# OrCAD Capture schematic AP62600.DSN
size Custom; title: 4.5V TO 18V INPUT, 6A SYNCHRONOUS BUCK CONVERTER; rev: 1.0; note: DS42003 Rev. 2 - 2
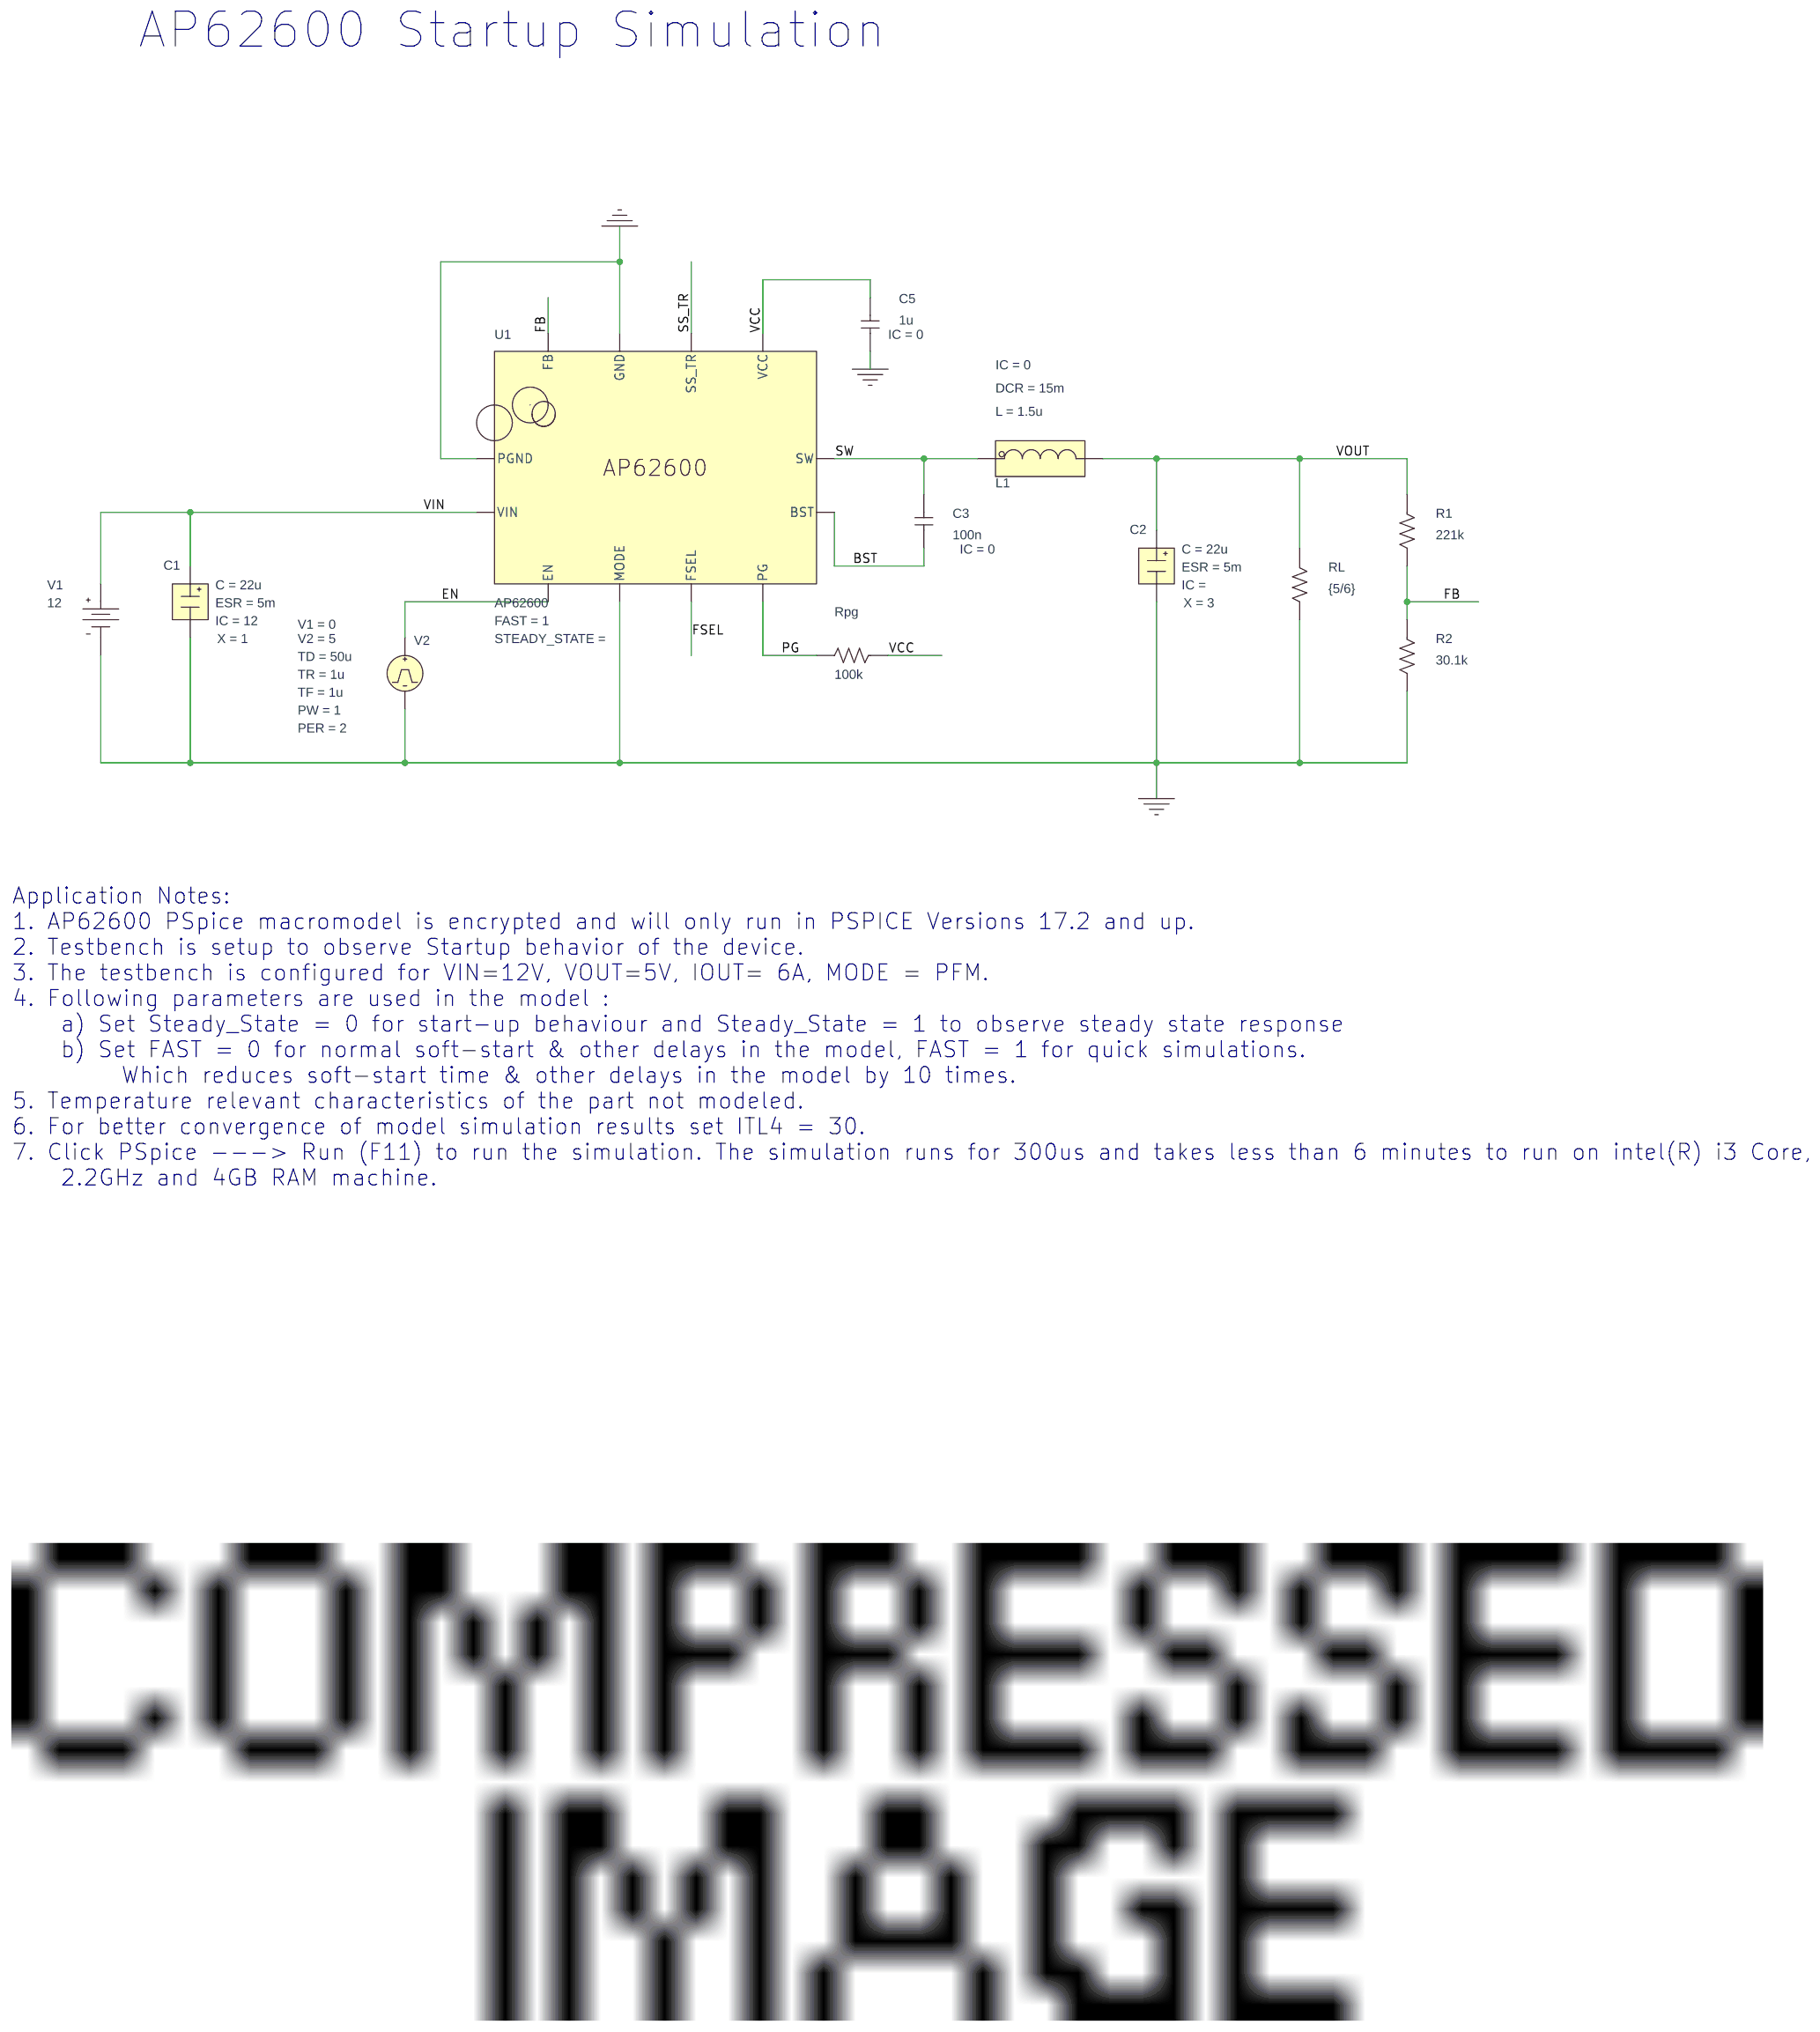
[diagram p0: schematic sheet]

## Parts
C1  CESR
C2  CESR
C3  100n  [RAD/CK05]
C5  1u  [RAD/CK05]
L1  LDCR
R1  221k  [AX/RC05]
R2  30.1k  [AX/RC05]
RL  {5/6}  [AX/RC05]
Rpg  100k  [AX/RC05]
U1  AP62600
V1  VDC
V2  VPULSE

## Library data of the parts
C1 = CESR: C: 22u; ESR: 5m; IC: 12; X: 1
C2 = CESR: C: 22u; ESR: 5m; X: 3
C3 C5 = C: IC: 0
L1 = LDCR: DCR: 15m; IC: 0; L: 1.5u; PSpiceTemplate: X^@REFDES %IN %OUT @MODEL PARAMS:  ?L|L=@L||L=1u|  ?DCR|DCR=@DCR||DCR=0.01| ?IC|IC=@IC||IC=0|
R1 R2 RL Rpg = R
U1 = AP62600: FAST: 1
V1 = VDC: DC: 12
V2 = VPULSE: PER: 2; PW: 1; TD: 50u; TF: 1u; TR: 1u; V1: 0; V2: 5

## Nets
VCC: C5.1 Rpg.1 U1.VCC
VIN: C1.1(IN) U1.VIN V1.0(+)
0: C1.3(OUT) C2.3(OUT) C5.2 R2.2 RL.2 U1.GND U1.MODE U1.PGND V1.1(-) V2.2(-)
BST: C3.1 U1.BST
EN: U1.EN V2.1(+)
FB: R1.2 R2.1 U1.FB
FSEL: U1.FSEL
PG: Rpg.2 U1.PG
SS_TR: U1.SS_TR
SW: C3.2 L1.1(IN) U1.SW
VOUT: C2.1(IN) L1.3(OUT) R1.1 RL.1

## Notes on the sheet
- AP62600 Startup Simulation
- Application Notes:
  1. AP62600 PSpice macromodel is encrypted and will only run in PSPICE Versions 17.2 and up.
  2. Testbench is setup to observe Startup behavior of the device.
  3. The testbench is configured for VIN=12V, VOUT=5V, IOUT= 6A, MODE = PFM.
  4. Following parameters are used in the model :
      a) Set Steady_State = 0 for start-up behaviour and Steady_State = 1 to observe steady state response
      b) Set FAST = 0 for normal soft-start & other delays in the model, FAST = 1 for quick simulations.
           Which reduces soft-start time & other delays in the model by 10 times.
  5. Temperature relevant characteristics of the part not modeled.
  6. For better convergence of model simulation results set ITL4 = 30.
  7. Click PSpice ---> Run (F11) to run the simulation. The simulation runs for 300us and takes less than 6 minutes to run on intel(R) i3 Core,
      2.2GHz and 4GB RAM machine.
